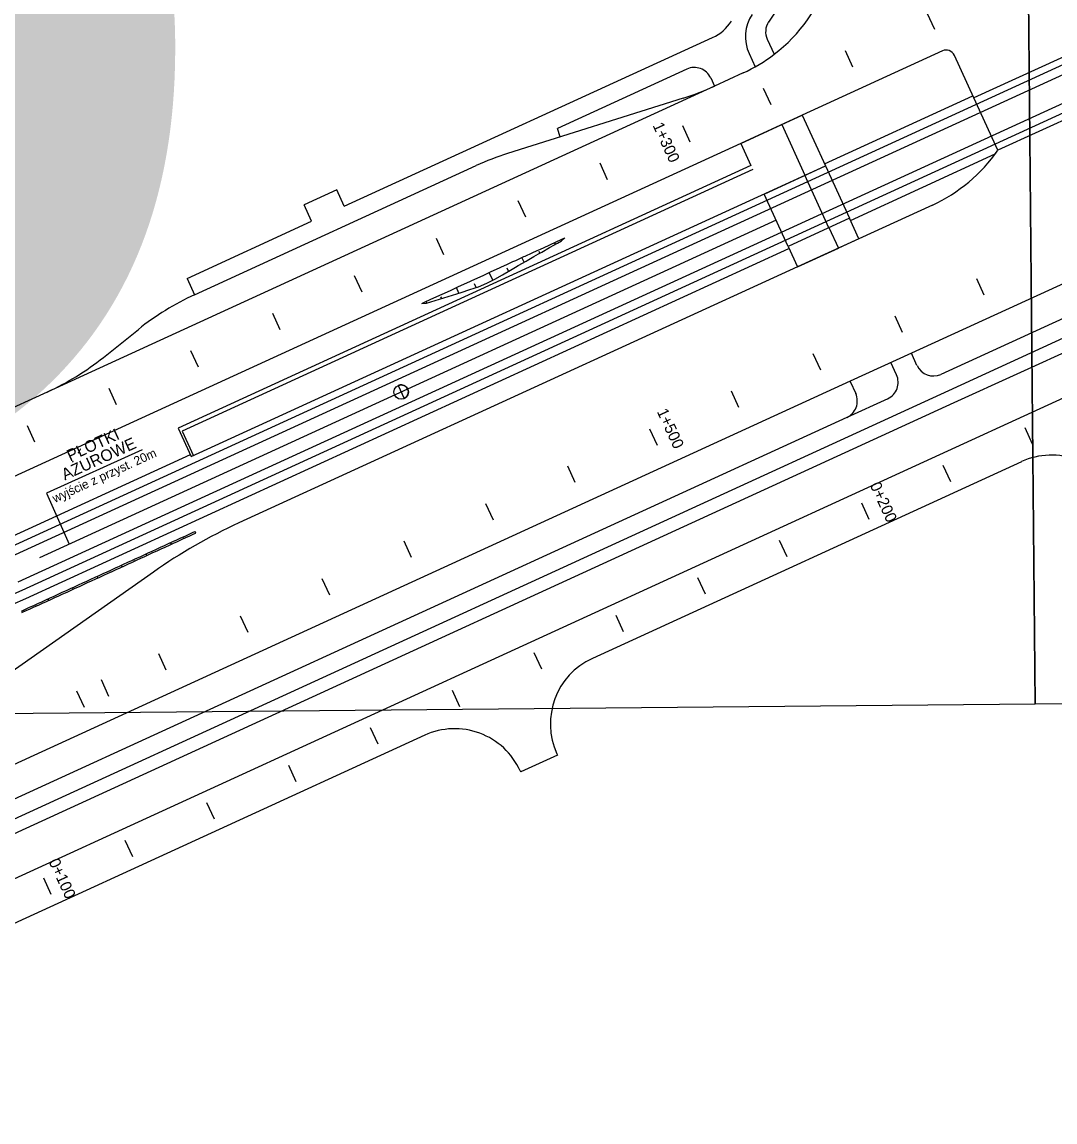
# Model space of a CAD drawing. Extents: x 6503541 to 6503743, y 5888004 to 5888145.
# Drawn here: x 6503624.343 to 6503627.098, y 5888063.051 to 5888065.985 of the extents above; entities that cross this region are included whole.
import ezdxf

# ---------------------------------------------------------------- set-up
doc = ezdxf.new("R2010")
doc.units = 0
doc.layers.add('12', color=7, linetype='Continuous')
doc.layers.add('tabela', color=7, linetype='Continuous')

msp = doc.modelspace()

# ---------------------------------------------------------------- linework, layer by layer
at = {"layer": '12'}
for p, q in [((6503624.2939, 5888064.5761), (6503641.7343, 5888072.5724)), ((6503624.3039, 5888064.5543), (6503641.7443, 5888072.5505)), ((6503624.3329, 5888064.491), (6503641.7733, 5888072.4873)), ((6503624.3429, 5888064.4692), (6503641.7833, 5888072.4655)), ((6503626.3771, 5888066.0508), (6503626.3338, 5888065.9845)), ((6503625.2024, 5888065.4929), (6503626.1843, 5888065.9432)), ((6503626.3303, 5888065.9383), (6503626.3486, 5888065.8984)), ((6503627.2232, 5888065.939), (6503626.8811, 5888065.7821)), ((6503627.2232, 5888065.939), (6503626.8811, 5888065.7821)), ((6503626.7973, 5888065.9074), (6503626.4231, 5888065.7358)), ((6503626.2818, 5888065.9005), (6503626.2981, 5888065.865)), ((6503626.8811, 5888065.7821), (6503626.8291, 5888065.8956)), ((6503626.1158, 5888065.859), (6503625.771, 5888065.7009)), ((6503626.2658, 5888065.8485), (6503626.1895, 5888065.8135)), ((6503626.1795, 5888065.8353), (6503626.1895, 5888065.8135)), ((6503626.1895, 5888065.8135), (6503624.4101, 5888064.9977)), ((6503626.4826, 5888065.606), (6503626.8786, 5888065.7876)), ((6503626.8786, 5888065.7876), (6503626.8811, 5888065.7821)), ((6503627.2872, 5888065.7993), (6503626.9452, 5888065.6425)), ((6503627.2872, 5888065.7993), (6503626.9452, 5888065.6425)), ((6503626.106, 5888065.7814), (6503625.6379, 5888065.6337)), ((6503626.9452, 5888065.6425), (6503626.8811, 5888065.7821)), ((6503626.9452, 5888065.6425), (6503626.8811, 5888065.7821)), ((6503626.4231, 5888065.7358), (6503626.2595, 5888065.6608)), ((6503626.3688, 5888065.7109), (6503626.4231, 5888065.7358)), ((6503626.4231, 5888065.7358), (6503626.4851, 5888065.6006)), ((6503625.7783, 5888065.678), (6503625.771, 5888065.7009)), ((6503626.2595, 5888065.6608), (6503626.3688, 5888065.7109)), ((6503626.3688, 5888065.7109), (6503626.4308, 5888065.5756)), ((6503626.2595, 5888065.6608), (6503622.6026, 5888063.9841)), ((6503626.2595, 5888065.6608), (6503626.2865, 5888065.6019)), ((6503626.5518, 5888065.4555), (6503626.9381, 5888065.6327)), ((6503626.2865, 5888065.6019), (6503624.7594, 5888064.9017)), ((6503626.2915, 5888065.591), (6503624.7698, 5888064.8933)), ((6503624.7944, 5888064.8254), (6503626.4852, 5888065.6006)), ((6503624.8031, 5888065.2571), (6503625.5544, 5888065.6015)), ((6503626.3216, 5888065.5256), (6503626.4852, 5888065.6006)), ((6503626.4852, 5888065.6006), (6503626.5493, 5888065.461)), ((6503626.4948, 5888065.436), (6503626.4308, 5888065.5756)), ((6503625.1824, 5888065.5366), (6503625.0951, 5888065.4966)), ((6503625.2024, 5888065.4929), (6503625.1824, 5888065.5366)), ((6503626.3857, 5888065.386), (6503626.3216, 5888065.5256)), ((6503627.6524, 5888065.5311), (6503626.7146, 5888065.1012)), ((6503627.9895, 5888065.5405), (6503626.8132, 5888065.0011)), ((6503625.1151, 5888065.4529), (6503625.0951, 5888065.4966)), ((6503626.7705, 5888065.4964), (6503626.5744, 5888065.4065)), ((6503627.8183, 5888065.5148), (6503626.7932, 5888065.0448)), ((6503628.0045, 5888065.5077), (6503626.8282, 5888064.9684)), ((6503624.783, 5888065.3007), (6503625.1151, 5888065.4529)), ((6503626.3536, 5888065.4558), (6503624.8263, 5888064.7555)), ((6503626.5493, 5888065.461), (6503626.3857, 5888065.386)), ((6503626.5493, 5888065.461), (6503626.3857, 5888065.386)), ((6503626.4947, 5888065.4361), (6503626.5198, 5888065.3815)), ((6503626.5744, 5888065.4065), (6503626.5493, 5888065.461)), ((6503626.5744, 5888065.4065), (6503626.4107, 5888065.3315)), ((6503626.5744, 5888065.4065), (6503626.5198, 5888065.3815)), ((6503624.3529, 5888064.4474), (6503626.3882, 5888065.3805)), ((6503626.3857, 5888065.386), (6503626.4107, 5888065.3315)), ((6503626.3857, 5888065.386), (6503626.4107, 5888065.3315)), ((6503626.4107, 5888065.3315), (6503626.5198, 5888065.3815)), ((6503626.4107, 5888065.3315), (6503624.9213, 5888064.6486)), ((6503624.783, 5888065.3007), (6503624.8031, 5888065.2571)), ((6503627.5672, 5888065.187), (6503623.1172, 5888063.1467)), ((6503624.5599, 5888065.09), (6503624.6533, 5888065.1647)), ((6503626.7146, 5888065.1011), (6503626.551, 5888065.0262)), ((6503626.7295, 5888065.0684), (6503626.7145, 5888065.1011)), ((6503626.675, 5888065.0434), (6503626.66, 5888065.0761)), ((6503626.551, 5888065.0262), (6503624.0486, 5888063.8788)), ((6503626.551, 5888065.0261), (6503626.566, 5888064.9934)), ((6503624.4101, 5888064.9977), (6503622.5325, 5888064.1368)), ((6503626.8132, 5888065.0011), (6503624.1036, 5888063.7588)), ((6503626.8282, 5888064.9684), (6503624.1186, 5888063.7261)), ((6503626.6514, 5888064.9797), (6503626.5424, 5888064.9298)), ((6503626.5424, 5888064.9298), (6503624.0836, 5888063.8025)), ((6503624.7594, 5888064.9017), (6503624.7944, 5888064.8254)), ((6503624.7698, 5888064.8933), (6503624.7998, 5888064.8279)), ((6503624.2839, 5888064.5979), (6503624.7919, 5888064.8308)), ((6503624.6633, 5888064.8438), (6503624.4078, 5888064.7276)), ((6503627.0081, 5888064.8119), (6503625.8639, 5888064.2873)), ((6503624.8263, 5888064.7555), (6503624.3899, 5888064.5554)), ((6503624.4078, 5888064.7276), (6503624.4687, 5888064.5916)), ((6503624.8068, 5888064.6216), (6503624.8048, 5888064.626)), ((6503624.7412, 5888064.5918), (6503624.7393, 5888064.596)), ((6503624.773, 5888064.6089), (6503624.774, 5888064.6068)), ((6503624.6758, 5888064.5618), (6503624.6739, 5888064.566)), ((6503624.7075, 5888064.5789), (6503624.7085, 5888064.5768)), ((6503624.6104, 5888064.5317), (6503624.6084, 5888064.536)), ((6503624.6421, 5888064.5489), (6503624.6431, 5888064.5467)), ((6503624.6932, 5888064.5176), (6503624.2296, 5888064.1916)), ((6503624.5449, 5888064.5017), (6503624.543, 5888064.506)), ((6503624.5767, 5888064.5189), (6503624.5776, 5888064.5167)), ((6503624.4794, 5888064.4718), (6503624.4775, 5888064.476)), ((6503624.5112, 5888064.4889), (6503624.5122, 5888064.4867)), ((6503624.414, 5888064.4418), (6503624.4121, 5888064.446)), ((6503624.4458, 5888064.4589), (6503624.4467, 5888064.4568)), ((6503624.3483, 5888064.4123), (6503624.3466, 5888064.416)), ((6503624.3803, 5888064.429), (6503624.3811, 5888064.4271)), ((6503625.4167, 5888064.0822), (6503623.1671, 5888063.0508)), ((6503625.7709, 5888064.0295), (6503625.6727, 5888063.9845)), ((6503625.7694, 5888064.0327), (6503625.7709, 5888064.0295)), ((6503625.6712, 5888063.9877), (6503625.6727, 5888063.9845))]:
    msp.add_line(p, q, dxfattribs=at)
for points in [[(6503626.777, 5888065.9641), (6503626.7569, 5888066.0077)], [(6503626.5588, 5888065.864), (6503626.5388, 5888065.9077)], [(6503626.3406, 5888065.764), (6503626.3206, 5888065.8076)], [(6503626.1041, 5888065.7084), (6503626.1241, 5888065.6647)], [(6503625.9043, 5888065.5639), (6503625.8843, 5888065.6076)], [(6503625.6861, 5888065.4639), (6503625.6661, 5888065.5076)], [(6503625.4088, 5888065.2338), (6503625.4216, 5888065.2347), (6503625.4447, 5888065.2419), (6503625.4678, 5888065.2491), (6503625.4909, 5888065.2563), (6503625.514, 5888065.2635), (6503625.5371, 5888065.2707), (6503625.5601, 5888065.2782), (6503625.5821, 5888065.2877), (6503625.6036, 5888065.2985), (6503625.6244, 5888065.3106), (6503625.6283, 5888065.3128), (6503625.6453, 5888065.3226), (6503625.659, 5888065.3305), (6503625.6662, 5888065.3347), (6503625.6871, 5888065.3467), (6503625.6898, 5888065.3482), (6503625.708, 5888065.3587), (6503625.7205, 5888065.3659), (6503625.7289, 5888065.3707), (6503625.7498, 5888065.3827), (6503625.7512, 5888065.3836), (6503625.7707, 5888065.3948), (6503625.7819, 5888065.4013), (6503625.7906, 5888065.4088)], [(6503625.4088, 5888065.2338), (6503625.4197, 5888065.2388), (6503625.4415, 5888065.2488), (6503625.4634, 5888065.2588), (6503625.4852, 5888065.2688), (6503625.507, 5888065.2788), (6503625.5288, 5888065.2888), (6503625.5506, 5888065.2988), (6503625.5724, 5888065.3088), (6503625.5943, 5888065.3188), (6503625.6161, 5888065.3288), (6503625.6201, 5888065.3307), (6503625.6379, 5888065.3388), (6503625.6522, 5888065.3454), (6503625.6597, 5888065.3488), (6503625.6815, 5888065.3588), (6503625.6843, 5888065.3601), (6503625.7033, 5888065.3688), (6503625.7164, 5888065.3748), (6503625.7252, 5888065.3788), (6503625.747, 5888065.3888), (6503625.7485, 5888065.3895), (6503625.7688, 5888065.3988), (6503625.7806, 5888065.4042), (6503625.7906, 5888065.4088)], [(6503625.468, 5888065.3639), (6503625.448, 5888065.4075)], [(6503625.7654, 5888065.3918), (6503625.7633, 5888065.3963)], [(6503625.6819, 5888065.3437), (6503625.6761, 5888065.3563)], [(6503625.7236, 5888065.3677), (6503625.7217, 5888065.372)], [(6503625.6401, 5888065.3196), (6503625.6363, 5888065.328)], [(6503625.2498, 5888065.2639), (6503625.2298, 5888065.3075)], [(6503625.5982, 5888065.2958), (6503625.5888, 5888065.3163)], [(6503626.909, 5888065.2563), (6503626.889, 5888065.2999)], [(6503625.5082, 5888065.2617), (6503625.5015, 5888065.2763)], [(6503625.5543, 5888065.2763), (6503625.5497, 5888065.2863)], [(6503625.4223, 5888065.2349), (6503625.4203, 5888065.2391)], [(6503625.462, 5888065.2473), (6503625.46, 5888065.2518)], [(6503625.0317, 5888065.1638), (6503625.0116, 5888065.2075)], [(6503626.6909, 5888065.1563), (6503626.6709, 5888065.1999)], [(6503624.8135, 5888065.0638), (6503624.7935, 5888065.1075)], [(6503626.4727, 5888065.0563), (6503626.4527, 5888065.0999)], [(6503624.5953, 5888064.9638), (6503624.5753, 5888065.0074)], [(6503625.346, 5888065.0149), (6503625.362, 5888064.98)], [(6503626.2546, 5888064.9562), (6503626.2346, 5888064.9999)], [(6503624.3772, 5888064.8638), (6503624.3572, 5888064.9074)], [(6503626.0164, 5888064.8998), (6503626.0364, 5888064.8562)], [(6503627.0378, 5888064.8585), (6503627.0178, 5888064.9021)], [(6503625.8182, 5888064.7562), (6503625.7982, 5888064.7998)], [(6503626.8196, 5888064.7585), (6503626.7996, 5888064.8021)], [(6503626.5815, 5888064.7021), (6503626.6015, 5888064.6585)], [(6503626.5815, 5888064.7021), (6503626.6015, 5888064.6585)], [(6503625.6001, 5888064.6562), (6503625.5801, 5888064.6998)], [(6503624.3411, 5888064.4135), (6503624.3521, 5888064.4185), (6503624.363, 5888064.4235), (6503624.374, 5888064.4285), (6503624.3849, 5888064.4335), (6503624.3958, 5888064.4385), (6503624.4067, 5888064.4435), (6503624.4176, 5888064.4485), (6503624.4285, 5888064.4535), (6503624.4394, 5888064.4585), (6503624.4503, 5888064.4635), (6503624.4612, 5888064.4685), (6503624.4721, 5888064.4735), (6503624.483, 5888064.4785), (6503624.4939, 5888064.4835), (6503624.5049, 5888064.4885), (6503624.5158, 5888064.4935), (6503624.5267, 5888064.4985), (6503624.5376, 5888064.5035), (6503624.5485, 5888064.5085), (6503624.5594, 5888064.5135), (6503624.5703, 5888064.5185), (6503624.5812, 5888064.5235), (6503624.5921, 5888064.5285), (6503624.603, 5888064.5335), (6503624.6139, 5888064.5385), (6503624.6248, 5888064.5435), (6503624.6358, 5888064.5485), (6503624.6467, 5888064.5535), (6503624.6576, 5888064.5585), (6503624.6685, 5888064.5635), (6503624.6794, 5888064.5685), (6503624.6903, 5888064.5735), (6503624.7012, 5888064.5785), (6503624.7121, 5888064.5836), (6503624.723, 5888064.5886), (6503624.7339, 5888064.5936), (6503624.7448, 5888064.5986), (6503624.7557, 5888064.6036), (6503624.7666, 5888064.6086), (6503624.7776, 5888064.6136), (6503624.7885, 5888064.6186), (6503624.7994, 5888064.6236), (6503624.8048, 5888064.626)], [(6503624.3428, 5888064.4099), (6503624.3538, 5888064.4148), (6503624.3648, 5888064.4197), (6503624.3757, 5888064.4246), (6503624.3867, 5888064.4295), (6503624.3976, 5888064.4344), (6503624.4086, 5888064.4393), (6503624.4195, 5888064.4443), (6503624.4304, 5888064.4493), (6503624.4413, 5888064.4543), (6503624.4522, 5888064.4593), (6503624.4632, 5888064.4643), (6503624.4741, 5888064.4693), (6503624.485, 5888064.4743), (6503624.4959, 5888064.4793), (6503624.5068, 5888064.4843), (6503624.5177, 5888064.4893), (6503624.5286, 5888064.4943), (6503624.5395, 5888064.4993), (6503624.5504, 5888064.5043), (6503624.5614, 5888064.5093), (6503624.5723, 5888064.5142), (6503624.5832, 5888064.5192), (6503624.5941, 5888064.5242), (6503624.605, 5888064.5292), (6503624.6159, 5888064.5342), (6503624.6268, 5888064.5393), (6503624.6377, 5888064.5443), (6503624.6486, 5888064.5493), (6503624.6595, 5888064.5543), (6503624.6704, 5888064.5593), (6503624.6813, 5888064.5643), (6503624.6922, 5888064.5693), (6503624.7031, 5888064.5743), (6503624.7141, 5888064.5793), (6503624.725, 5888064.5843), (6503624.7359, 5888064.5893), (6503624.7468, 5888064.5943), (6503624.7577, 5888064.5993), (6503624.7686, 5888064.6043), (6503624.7795, 5888064.6094), (6503624.7904, 5888064.6143), (6503624.8014, 5888064.6192), (6503624.8068, 5888064.6216)], [(6503625.3819, 5888064.5561), (6503625.3619, 5888064.5998)], [(6503626.3833, 5888064.5584), (6503626.3633, 5888064.6021)], [(6503625.1637, 5888064.4561), (6503625.1437, 5888064.4997)], [(6503626.1652, 5888064.4584), (6503626.1452, 5888064.502)], [(6503624.9456, 5888064.3561), (6503624.9256, 5888064.3997)], [(6503625.947, 5888064.3584), (6503625.927, 5888064.402)], [(6503624.7274, 5888064.256), (6503624.7074, 5888064.2997)], [(6503625.7288, 5888064.2584), (6503625.7088, 5888064.302)], [(6503624.5747, 5888064.186), (6503624.5547, 5888064.2297)], [(6503625.5107, 5888064.1583), (6503625.4907, 5888064.202)], [(6503624.5093, 5888064.156), (6503624.4893, 5888064.1997)], [(6503625.2925, 5888064.0583), (6503625.2725, 5888064.1019)], [(6503625.0743, 5888063.9583), (6503625.0543, 5888064.0019)], [(6503624.8562, 5888063.8583), (6503624.8362, 5888063.9019)], [(6503624.638, 5888063.7582), (6503624.618, 5888063.8019)], [(6503624.3999, 5888063.7018), (6503624.4199, 5888063.6582)], [(6503624.3999, 5888063.7018), (6503624.4199, 5888063.6582)]]:
    msp.add_lwpolyline(points, dxfattribs=at)
msp.add_circle((6503625.354, 5888064.9975), 0.0192, dxfattribs=at)
for centre, radius, start, end in [((6503626.0858, 5888066.2412), 0.432, 307.4706, 15.037), ((6503626.38, 5888065.9455), 0.108, 146.8353, 204.6311), ((6503626.1343, 5888066.0522), 0.12, 294.6311, 326.8353), ((6503626.3739, 5888065.9583), 0.048, 146.8353, 204.6311), ((6503626.8073, 5888065.8856), 0.024, 24.6311, 114.6311), ((6503626.0858, 5888066.2412), 0.432, 294.6311, 307.4706), ((6503626.1359, 5888065.8153), 0.048, 24.6311, 114.6311), ((6503625.8894, 5888066.468), 0.72, 287.506, 294.6311), ((6503626.5905, 5888065.8891), 0.432, 294.6311, 325.1895), ((6503626.5905, 5888065.8891), 0.432, 323.5861, 325.1895), ((6503625.8545, 5888064.9471), 0.72, 107.506, 114.6311), ((6503625.1031, 5888064.6026), 0.72, 114.6311, 128.6673), ((6503624.1101, 5888065.6522), 0.72, 294.6311, 308.6673), ((6503626.7732, 5888065.0884), 0.048, 204.6716, 294.6311), ((6503626.6313, 5888065.0234), 0.048, 294.6311, 24.6716), ((6503625.354, 5888064.9975), 0.0192, 350.1838, 114.6311), ((6503625.354, 5888064.9975), 0.0192, 294.6311, 350.1838), ((6503626.5224, 5888064.9734), 0.048, 294.6311, 24.6716), ((6503627.0881, 5888064.6374), 0.192, 23.7826, 114.6311), ((6503625.5215, 5888063.3396), 1.44, 114.6311, 125.1123), ((6503614.3158, 5888086.3389), 24.0588, 291.63106, 294.63106), ((6503614.3158, 5888086.3389), 24.0828, 291.63106, 294.63106), ((6503625.9439, 5888064.1128), 0.192, 114.6311, 204.6311), ((6503625.4967, 5888063.9077), 0.192, 24.6311, 114.6311)]:
    msp.add_arc(centre, radius, start, end, dxfattribs=at)
at = {"layer": 'tabela'}
for p, q in [((6503627.0449, 5888064.165), (6503626.998, 5888069.1851)), ((6503626.998, 5888069.1851), (6503627.0449, 5888064.165)), ((6503634.2803, 5888064.2326), (6503627.0449, 5888064.165)), ((6503627.0449, 5888064.165), (6503619.8094, 5888064.0974))]:
    msp.add_line(p, q, dxfattribs=at)

# ---------------------------------------------------------------- texts
at = {"layer": '12'}
for s, height, rotation, p in [('8', 4.223, 0.7393, (6503621.8715, 5888064.7245)), ('1+300', 0.03, 294.6311, (6503626.024, 5888065.7089)), ('1+500', 0.03, 294.6311, (6503626.0352, 5888064.9457)), ('AŻUROWE', 0.0311, 24.5449, (6503624.4571, 5888064.7614)), ('PŁOTKI', 0.0311, 24.5449, (6503624.4712, 5888064.812)), ('wyjście z przyst. 20m', 0.023802, 24.5449, (6503624.4306, 5888064.7018)), ('0+200', 0.03, 294.6311, (6503626.6033, 5888064.7493)), ('0+100', 0.03, 294.6311, (6503624.4134, 5888063.7453))]:
    msp.add_text(s, height=height, rotation=rotation, dxfattribs=at).set_placement(p)

doc.saveas('drawing.dxf')
